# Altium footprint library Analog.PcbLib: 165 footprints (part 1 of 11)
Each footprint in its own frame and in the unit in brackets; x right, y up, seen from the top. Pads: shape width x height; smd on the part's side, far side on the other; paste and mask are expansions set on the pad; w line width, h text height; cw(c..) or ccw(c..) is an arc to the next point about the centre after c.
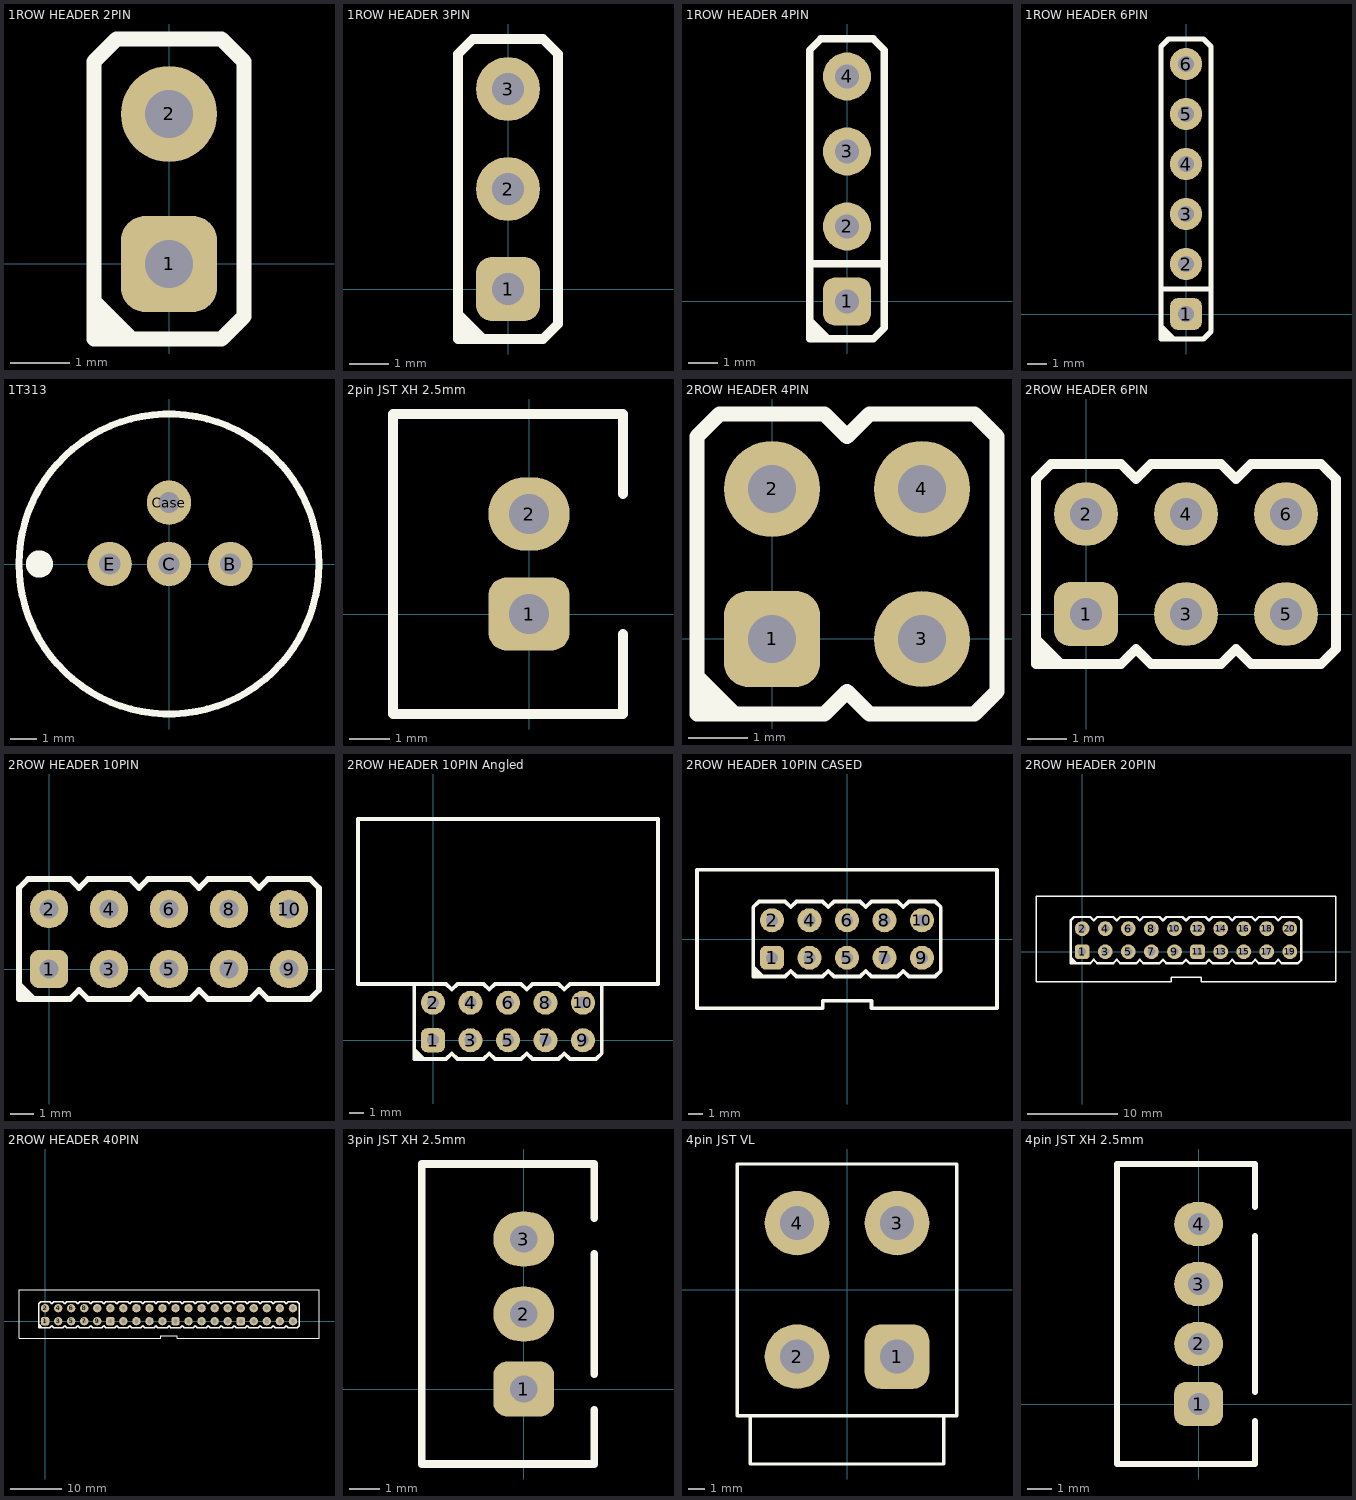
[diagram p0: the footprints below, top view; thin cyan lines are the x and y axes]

## 1ROW HEADER 2PIN [mil] "PEC02SAAN"
pads (2):
  rrect50% 64x64 hole 32: 1(0,0)
  round 64 hole 32: 2(0,100)
Top Overlay:
  lines w10: -50,-35 -35,-50 ; -50,-25 -25,-50 ; -50,-50 35,-50 50,-35 50,135 35,150 -35,150 -50,135 -50,-50

## 1ROW HEADER 3PIN [mil] "PEC03SAAN"
height 300
pads (3):
  rrect50% 64x64 hole 32: 1(0,0)
  round 64 hole 32: 2(0,100) 3(0,200)
Top Overlay:
  lines w10: -50,-35 -35,-50 ; -50,-25 -25,-50 ; -50,-50 35,-50 50,-35 50,235 35,250 -35,250 -50,235 -50,-50

## 1ROW HEADER 4PIN [mil] "PEC04SAAN"
height 300
pads (4):
  rrect50% 64x64 hole 32: 1(0,0)
  round 64 hole 32: 2(0,100) 3(0,200) 4(0,300)
Top Overlay:
  lines w10: -50,-35 -35,-50 ; -50,-25 -25,-50 ; -50,50 50,50 ; -50,-50 -50,335 -35,350 35,350 50,335 50,-35 35,-50 -50,-50

## 1ROW HEADER 6PIN [mil] "PEC06SAAN"
height 300
pads (6):
  rrect50% 64x64 hole 32: 1(0,0)
  round 64 hole 32: 2(0,100) 3(0,200) 4(0,300) 5(0,400) 6(0,500)
Top Overlay:
  lines w10: -50,-35 -35,-50 ; -50,-25 -25,-50 ; -50,50 50,50 ; -50,-50 35,-50 50,-35 50,535 35,550 -35,550 -50,535 -50,-50

## 1T313 [mil]
height 400
pads (4):
  round 65 hole 31: B(90,0) C(0,0) Case(0,90) E(-87,0)
Top Overlay:
  circle w10: c0,0 r220
  circle w20: c-190,0 r10

## 2pin JST XH 2.5mm [mil] "B2B-XH"
height 275.59
pads (2):
  rrect50% 80x72 hole 39.37: 1(0,0)
  oval 80x72 hole 39.37: 2(0,98.43)
Top Overlay:
  lines w10: 92.52,-19.68 92.52,-98.43 -133.86,-98.43 -133.86,196.85 92.52,196.85 92.52,118.11

## 2ROW HEADER 4PIN [mil] "PEC02SAAN"
pads (4):
  rrect50% 64x64 hole 32: 1(0,0)
  round 64 hole 32: 2(0,100) 3(100,0) 4(100,100)
Top Overlay:
  lines w10: -50,-35 -35,-50 ; -50,-25 -25,-50 ; -50,-50 -50,135 -35,150 35,150 50,135 65,150 135,150 150,135 150,-35 135,-50 65,-50 50,-35 35,-50 -50,-50

## 2ROW HEADER 6PIN [mil]
pads (6):
  rrect50% 64x64 hole 32: 1(0,0)
  round 64 hole 32: 2(0,100) 3(100,0) 4(100,100) 5(200,0) 6(200,100)
Top Overlay:
  lines w10: -50,-35 -35,-50 ; -50,-25 -25,-50 ; -50,-50 -50,135 -35,150 35,150 50,135 65,150 135,150 150,135 165,150 235,150 250,135 250,-35 235,-50 165,-50 150,-35 135,-50 65,-50 50,-35 35,-50 -50,-50

## 2ROW HEADER 10PIN [mil] "PEC02SAAN"
pads (10):
  rrect50% 64x64 hole 32: 1(0,0)
  round 64 hole 32: 2(0,100) 3(100,0) 4(100,100) 5(200,0) 6(200,100) 7(300,0) 8(300,100) 9(400,0) 10(400,100)
Top Overlay:
  lines w10: -50,-35 -35,-50 ; -50,-25 -25,-50 ; -50,-50 -50,135 -35,150 35,150 50,135 65,150 135,150 150,135 165,150 235,150 250,135 265,150 335,150 350,135 365,150 435,150 450,135 450,-35 435,-50 365,-50 350,-35 335,-50 265,-50 250,-35 235,-50 165,-50 150,-35 135,-50 65,-50 50,-35 35,-50 -50,-50

## 2ROW HEADER 10PIN Angled [mil] "2X05P"
height 400
pads (10):
  rrect50% 64x64 hole 32: 1(0,0)
  round 64 hole 32: 2(0,100) 3(100,0) 4(100,100) 5(200,0) 6(200,100) 7(300,0) 8(300,100) 9(400,0) 10(400,100)
Top Overlay:
  lines w10: -50,-35 -35,-50 ; -50,-25 -25,-50 ; -50,150 35,150 50,135 65,150 135,150 150,135 165,150 235,150 250,135 265,150 335,150 350,135 365,150 450,150 ; -50,150 -50,-50 35,-50 50,-35 65,-50 135,-50 150,-35 165,-50 235,-50 250,-35 265,-50 335,-50 350,-35 365,-50 435,-50 450,-35 450,150 ; -50,150 -200,150 -200,590 600,590 600,150 450,150

## 2ROW HEADER 10PIN CASED [mil] "PEC02SAAN"
pads (10):
  rrect50% 64x64 hole 32: 1(-200,-50)
  round 64 hole 32: 2(-200,50) 3(-100,-50) 4(-100,50) 5(0,-50) 6(0,50) 7(100,-50) 8(100,50) 9(200,-50) 10(200,50)
Top Overlay:
  lines w10: -250,-85 -235,-100 ; -250,-75 -225,-100 ; -400,-185 -400,185 400,185 400,-185 65,-185 65,-165 -65,-165 -65,-185 -400,-185 ; -250,-100 -250,85 -235,100 -165,100 -150,85 -135,100 -65,100 -50,85 -35,100 35,100 50,85 65,100 135,100 150,85 165,100 235,100 250,85 250,-85 235,-100 165,-100 150,-85 135,-100 65,-100 50,-85 35,-100 -35,-100 -50,-85 -65,-100 -135,-100 -150,-85 -165,-100 -250,-100

## 2ROW HEADER 20PIN [mil]
height 200
pads (20):
  rrect50% 64x64 hole 35: 1(0,0) 11(500,0)
  round 64 hole 35: 2(0,100) 3(100,0) 4(100,100) 5(200,0) 6(200,100) 7(300,0) 8(300,100) 9(400,0) 10(400,100) 12(500,100) 13(600,0) 14(600,100) 15(700,0) 16(700,100) 17(800,0) 18(800,100) 19(900,0) 20(900,100)
Top Overlay:
  lines w6: -200,-130 385,-130 385,-110 515,-110 515,-130 1100,-130 1100,240 -200,240 -200,-130
  lines w10: -50,-35 -35,-50 ; -50,-25 -25,-50 ; -50,-50 -50,135 -35,150 35,150 50,135 65,150 135,150 150,135 165,150 235,150 250,135 265,150 335,150 350,135 365,150 435,150 450,135 465,150 535,150 550,135 565,150 635,150 650,135 665,150 735,150 750,135 765,150 835,150 850,135 865,150 935,150 950,135 950,-35 935,-50 865,-50 850,-35 835,-50 765,-50 750,-35 735,-50 665,-50 650,-35 635,-50 565,-50 550,-35 535,-50 465,-50 450,-35 435,-50 365,-50 350,-35 335,-50 265,-50 250,-35 235,-50 165,-50 150,-35 135,-50 65,-50 50,-35 35,-50 -50,-50

## 2ROW HEADER 40PIN [mil]
height 200
pads (40):
  rrect50% 64x64 hole 32: 1(0,0) 11(500,0) 21(1000,0) 31(1500,0)
  round 64 hole 32: 2(0,100) 3(100,0) 4(100,100) 5(200,0) 6(200,100) 7(300,0) 8(300,100) 9(400,0) 10(400,100) 12(500,100) 13(600,0) 14(600,100) 15(700,0) 16(700,100) 17(800,0) 18(800,100) 19(900,0) 20(900,100) 22(1000,100) 23(1100,0) 24(1100,100) 25(1200,0) 26(1200,100) 27(1300,0) 28(1300,100) 29(1400,0) 30(1400,100) 32(1500,100) 33(1600,0) 34(1600,100) 35(1700,0) 36(1700,100) 37(1800,0) 38(1800,100) 39(1900,0) 40(1900,100)
Top Overlay:
  lines w6: -200,-130 -200,240 2100,240 2100,-130 1015,-130 1015,-110 885,-110 885,-130 -200,-130
  lines w10: -50,-35 -35,-50 ; -50,-25 -25,-50 ; -50,-50 -50,135 -35,150 35,150 50,135 65,150 135,150 150,135 165,150 235,150 250,135 265,150 335,150 350,135 365,150 435,150 450,135 465,150 535,150 550,135 565,150 635,150 650,135 665,150 735,150 750,135 765,150 835,150 850,135 865,150 935,150 950,135 965,150 1035,150 1050,135 1065,150 1135,150 1150,135 1165,150 1235,150 1250,135 1265,150 1335,150 1350,135 1365,150 1435,150 1450,135 1465,150 1535,150 1550,135 1565,150 1635,150 1650,135 1665,150 1735,150 1750,135 1765,150 1835,150 1850,135 1865,150 1935,150 1950,135 1950,-35 1935,-50 1865,-50 1850,-35 1835,-50 1765,-50 1750,-35 1735,-50 1665,-50 1650,-35 1635,-50 1565,-50 1550,-35 1535,-50 1465,-50 1450,-35 1435,-50 1365,-50 1350,-35 1335,-50 1265,-50 1250,-35 1235,-50 1165,-50 1150,-35 1135,-50 1065,-50 1050,-35 1035,-50 965,-50 950,-35 935,-50 865,-50 850,-35 835,-50 765,-50 750,-35 735,-50 665,-50 650,-35 635,-50 565,-50 550,-35 535,-50 465,-50 450,-35 435,-50 365,-50 350,-35 335,-50 265,-50 250,-35 235,-50 165,-50 150,-35 135,-50 65,-50 50,-35 35,-50 -50,-50

## 3pin JST XH 2.5mm [mil] "B3B-XH"
height 275.59
pads (3):
  rrect50% 80x72 hole 35.43: 1(0,0)
  oval 80x72 hole 35.43: 2(0,98.43) 3(0,196.85)
Top Overlay:
  lines w10: 92.52,-27.56 92.52,-98.43 -133.86,-98.43 -133.86,295.28 92.52,295.28 92.52,224.41 ; 92.52,19.68 92.52,177.17

## 4pin JST VL [mm] "B04P-VL"
height 29.2
pads (4):
  rrect50% 4x4 hole 2.1: 1(3.1,-4.14)
  round 4 hole 2.1: 2(-3.1,-4.14) 3(3.1,4.14) 4(-3.1,4.14)
Top Overlay:
  lines w0.203: -6,-7.8 -6,-10.8 6,-10.8 6,-7.8 ; -6.8,-7.8 -6.8,7.8 6.8,7.8 6.8,-7.8 -6.8,-7.8

## 4pin JST XH 2.5mm [mil] "B4B-XH"
height 275.59
pads (4):
  rrect50% 80x72 hole 35.43: 1(0,0)
  oval 80x72 hole 35.43: 2(0,98.43) 3(0,196.85) 4(0,295.28)
Top Overlay:
  lines w10: 92.52,-27.56 92.52,-98.43 -133.86,-98.43 -133.86,393.7 92.52,393.7 92.52,322.83 ; 92.52,19.68 92.52,275.59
